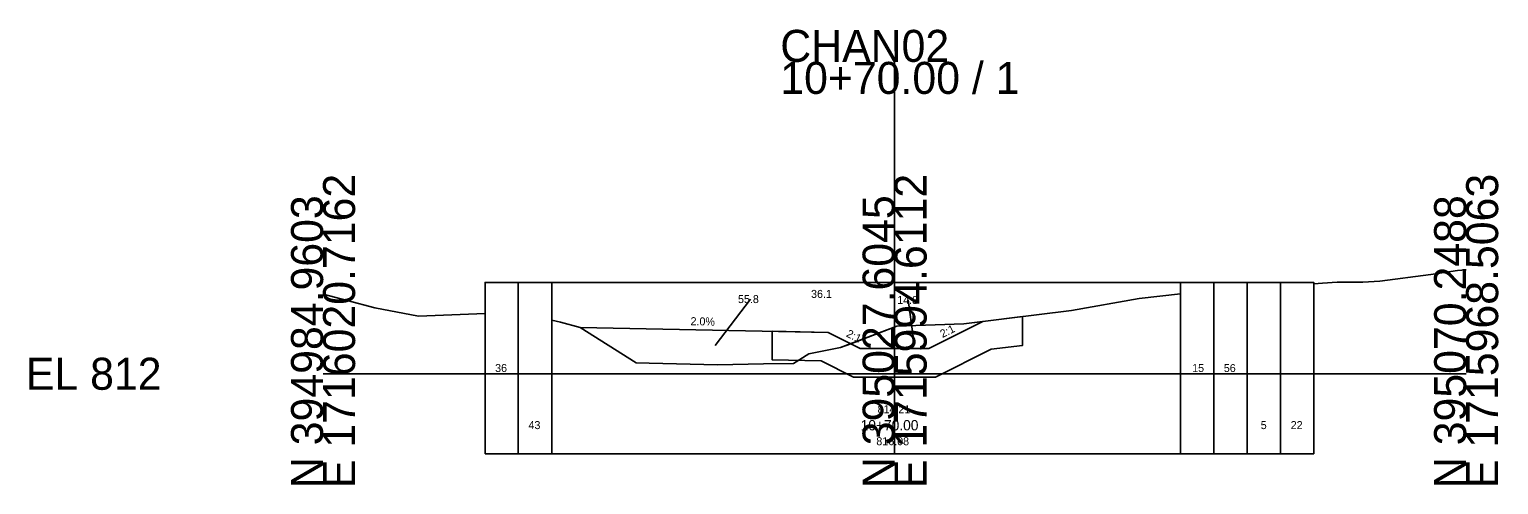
# Model space of a CAD drawing. Extents: x -26 to 103, y -10 to 16052.
# Drawn here: x -25.7 to 102.8, y 9990.3 to 10030.1 of the extents above; entities that cross this region are included whole.
import ezdxf

# ---------------------------------------------------------------- set-up
doc = ezdxf.new("R2010")
doc.units = 0
for name, color, linetype in [('GK_Cells', 7, 'Continuous'), ('SC_Scratch17', 7, 'Continuous'), ('SH_Text', 7, 'Continuous'), ('XS_P_Annotation', 7, 'Continuous'), ('XS_P_Boundary', 7, 'Continuous'), ('XS_P_Earthwork_Shapes', 7, 'Continuous'), ('XS_P_Finished_Grade', 7, 'Continuous'), ('XS_X_Ground_Line', 7, 'Continuous')]:
    doc.layers.add(name, color=color, linetype=linetype)

msp = doc.modelspace()

# ---------------------------------------------------------------- linework, layer by layer
at = {"layer": 'GK_Cells'}
for p, q in [((50, 10000), (50, 10027.27)), ((0, 10000), (50, 10000)), ((50, 10000), (100, 10000))]:
    msp.add_line(p, q, dxfattribs=at)
at = {"layer": 'SC_Scratch17'}
msp.add_lwpolyline([(39.29, 10003.72), (44.19, 10003.62), (47, 10002.21), (50, 10002.21), (53, 10002.21), (57.73, 10004.57), (61.2, 10005), (61.2, 10002.48), (58.46, 10002.14), (53.59, 9999.71), (46.41, 9999.71), (43.57, 10001.13), (39.29, 10001.21)], close=True, dxfattribs=at)
at = {"layer": 'XS_P_Boundary'}
for p, q in [((17.08, 9993.01), (17.08, 10007.99)), ((20, 9993.01), (20, 10007.99)), ((50, 9993.01), (50, 10007.99)), ((75, 9993.01), (75, 10007.99)), ((77.92, 9993.01), (77.92, 10007.99)), ((80.83, 9993.01), (80.83, 10007.99)), ((83.75, 9993.01), (83.75, 10007.99)), ((15.63, 10000.5), (15.63, 10000.5)), ((76.46, 10000.5), (76.46, 10000.5)), ((79.38, 10000.5), (79.38, 10000.5)), ((18.54, 9995.51), (18.54, 9995.51)), ((82.29, 9995.51), (82.29, 9995.51)), ((85.21, 9995.51), (85.21, 9995.51))]:
    msp.add_line(p, q, dxfattribs=at)
msp.add_lwpolyline([(14.17, 9993.01), (14.17, 10007.99), (86.67, 10007.99), (86.67, 9993.01)], close=True, dxfattribs=at)
at = {"layer": 'XS_P_Earthwork_Shapes'}
for p, q in [((34.29, 10002.46), (37.39, 10006.53)), ((51.61, 10003.25), (51.18, 10006.45)), ((44.19, 10003.62), (22.48, 10004.05)), ((53, 10002.21), (57.73, 10004.57)), ((57.73, 10004.57), (56.06, 10004.37)), ((46.16, 10002.63), (44.19, 10003.62)), ((46.16, 10002.63), (47, 10002.21)), ((47, 10002.21), (50, 10002.21)), ((50, 10002.21), (53, 10002.21))]:
    msp.add_line(p, q, dxfattribs=at)
for points in [[(22.48, 10004.05), (44.19, 10003.62), (47, 10002.21), (53, 10002.21), (57.73, 10004.57)], [(22.48, 10004.05), (27.38, 10000.96), (28.52, 10000.93), (34.51, 10000.77), (38.53, 10000.87), (41.15, 10000.91), (42.51, 10001.73), (45.27, 10002.3), (46.16, 10002.63)], [(56.06, 10004.37), (50.18, 10004.15), (46.16, 10002.63)]]:
    msp.add_lwpolyline(points, dxfattribs=at)
at = {"layer": 'XS_P_Finished_Grade'}
for p, q in [((44.19, 10003.62), (22.48, 10004.05)), ((57.73, 10004.57), (53, 10002.21)), ((44.19, 10003.62), (47, 10002.21)), ((47, 10002.21), (53, 10002.21))]:
    msp.add_line(p, q, dxfattribs=at)
at = {"layer": 'XS_X_Ground_Line'}
for points in [[(86.67, 10007.85), (87.43, 10007.91), (88.72, 10008.01), (90.97, 10008.02), (92.44, 10008.1), (96.9, 10008.67), (99.24, 10009.02), (100, 10009.09)], [(0, 10006.96), (2.11, 10006.42), (4.52, 10005.76), (8.34, 10005.05), (14.17, 10005.26)], [(20, 10004.68), (20.78, 10004.52), (22.48, 10004.05), (27.38, 10000.96), (28.52, 10000.93), (34.51, 10000.77), (38.53, 10000.87), (41.15, 10000.91), (42.51, 10001.73), (45.27, 10002.3), (50.18, 10004.15), (56.06, 10004.37), (65.46, 10005.52), (71.4, 10006.59), (75, 10006.99)]]:
    msp.add_lwpolyline(points, dxfattribs=at)

# ---------------------------------------------------------------- texts
at = {"layer": 'GK_Cells'}
for s, p in [('CHAN02', (40, 10027.27)), ('10+70.00 / 1', (40, 10024.47)), ('EL 812', (-26, 9998.6))]:
    msp.add_text(s, height=2.8, dxfattribs=at).set_placement(p)
for s, p in [('E 1716020.7162', (2.8, 9990)), ('E 1715994.6112', (52.8, 9990)), ('E 1715968.5063', (102.8, 9990)), ('N 394984.9603', (0, 9990)), ('N 395027.6045', (50, 9990)), ('N 395070.2488', (100, 9990))]:
    msp.add_text(s, height=2.8, rotation=90, dxfattribs=at).set_placement(p)
at = {"layer": 'SH_Text'}
for s, p in [('36', (15.05, 10000.15)), ('15', (76.03, 10000.15)), ('56', (78.8, 10000.15)), ('43', (17.97, 9995.16)), ('5', (82.03, 9995.16)), ('22', (84.65, 9995.16))]:
    msp.add_text(s, height=0.7, dxfattribs=at).set_placement(p)
at = {"layer": 'XS_P_Annotation'}
for s, rotation, p in [('2.0%', 358.8542, (32.14, 10004.25)), ('2:1', 333.4349, (45.71, 10003.28)), ('2:1', 26.5651, (54.19, 10003.12))]:
    msp.add_text(s, height=0.7, rotation=rotation, dxfattribs=at).set_placement(p)
for s, height, p in [('814.21', 0.7, (48.51, 9996.55)), ('10+70.00', 0.9, (47.03, 9995.05)), ('816.08', 0.7, (48.4, 9993.75))]:
    msp.add_text(s, height=height, dxfattribs=at).set_placement(p)
at = {"layer": 'XS_P_Earthwork_Shapes'}
for s, p in [('55.8', (36.3, 10006.18)), ('36.1', (42.69, 10006.63)), ('14.8', (50.23, 10006.1))]:
    msp.add_text(s, height=0.7, dxfattribs=at).set_placement(p)

doc.saveas('drawing.dxf')
